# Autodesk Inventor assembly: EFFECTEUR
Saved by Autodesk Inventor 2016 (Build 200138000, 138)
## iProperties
Created: 2013-10
Part Number: EFFECTEUR
Material: Générique
Document SubType Name: Assembly
Designer: Bruno
Author: Bruno
Sending System: SolidWorks 2013
Last Author: christophe
Last Saved: 2014-02-15
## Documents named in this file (2)
- D:\Cours\Systèmes SI\Robot Haptique\Documentations_pedagogique\Modèle solidworks\Réel\EFFECTEUR.iam
- D:\Cours\Systèmes SI\Robot Haptique\Documentations_pedagogique\Modèle solidworks\Réel\BASE.ipt
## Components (1 placed, 1 different names)
1. BASE:1
